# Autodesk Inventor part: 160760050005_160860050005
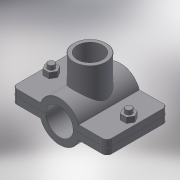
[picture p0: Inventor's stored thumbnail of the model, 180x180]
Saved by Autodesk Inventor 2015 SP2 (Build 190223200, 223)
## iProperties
Created: 2017-05
Part Number: 160760050005_160860050005
Material: Generic
Description: PLASSON SADDLE 50-1/2"
Document SubType Name: Modeling
Designer: KIM
Density: 1 g/cm^3
Appearance: Default
Author: KIM
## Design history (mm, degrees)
derived "16076.ipt"
feature "Solid1::16076.ipt"
feature "Solid2::16076.ipt"
tag "TaggingFeature1"
body "Solid1"
other parameters: "d1" = 106, "d2" = 25, "d4" = 73, "d5" = 0, "d6" = 5.3, "d7" = 106, "d8" = 0.1, "d10" = 0, "d11" = 0.5, "d14" = 24.2203, "d20" = 0.5, "d23" = 0.5, "d37" = 8, "d38" = 33, "d39" = 0, "d40" = 3, "d41" = 5, "d42" = 0, "d43" = 6, "d44" = 3, "d45" = 0, "d46" = 0.5, "d51" = 51, "d52" = 18.631, "d53" = 18, "d54" = 0, "d55" = 16, "d57" = 0, "d58" = 54, "d60" = 0, "d63" = 36.5, "d66" = 0, "B_" = 16, "G_" = 18.631, "A_" = 51, "L_" = 106, "L_1" = 73, "l_2" = 18
